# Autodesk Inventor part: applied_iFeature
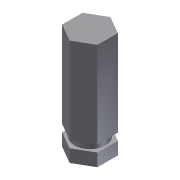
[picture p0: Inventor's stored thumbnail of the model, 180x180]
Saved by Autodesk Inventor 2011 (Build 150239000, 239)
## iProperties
Created: 2008-06
Part Number: applied_iFeature
Document SubType Name: Modeling
Designer: CADCIM
Density: 1 g/cm^3
Author: CADCIM
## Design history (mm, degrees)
sketch "Sketch1"
  geometry: L1 (0, 28.868)-(25, 14.434); L2 (25, 14.434)-(25, -14.434); L3 (25, -14.434)-(0, -28.868); L4 (0, -28.868)-(-25, -14.434); L5 (-25, -14.434)-(-25, 14.434); L6 (-25, 14.434)-(0, 28.868); 1 further point
  constraints: 12 end point, 1 vertical, 14 other
  dimensions: "d0" = 50 distance between parallel lines of L2 L5
extrude "Extrusion1" new body sketch "Sketch1" distance "d1" = 150; taper "d2" = 0 deg
feature "iFeature1:1"
body "Solid1"
